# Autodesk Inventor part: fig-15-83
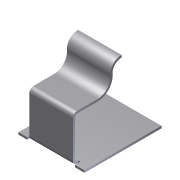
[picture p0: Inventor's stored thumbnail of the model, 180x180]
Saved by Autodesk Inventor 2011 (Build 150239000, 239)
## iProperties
Shininess: 77.0
Angle Display Precision: 2
Document Length Units: 11269
Document Angle Units: 11279
Document Time Units: 11290
Document Mass Units: 11283
Document Length Units Precision: 3
Document Angle Units Precision: 2
Compacted: True
Created: 2002-04
Part Number: fig-15-83
Document SubType Name: Sheet Metal
Density: 1 g/cm^3
Sheet Metal Rule: Default
Density: 0.0
Volumn: 0.0
Area: 0.0
PropertySet Name: Model Information
Control State: 0
Master: False
Checked Out: False
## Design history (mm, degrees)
node "Face1"
  sketch "Sketch1"
    geometry: L1 (-24.824, 17.882)-(5.529, 17.882); L2 (5.529, 17.882)-(5.529, -17.529); L3 (5.529, -17.529)-(-24.824, -17.529); L4 (-24.824, -17.529)-(-24.824, 17.882)
    constraints: 8 end point, 2 parallel, 1 horizontal, 1 perpendicular
node "Flange1"
node "Contour Flange6"
  sketch "Sketch5"
    geometry: L1 (0, 1)-(0, 11.431); A1 r 5.855 centre (-5.855, 11.431) between (0, 11.431) and (-6.422, 17.259); A2 r 5.142 centre (-6.92, 22.376) between (-12.062, 22.382) and (-6.422, 17.259)
    constraints: 4 point on circle, 2 centre point, 2 end point, 2 tangent
body "Solid1"
face "Plate1" dims "Thickness" = 1
sketch "Sketch3"
  geometry: L1 (25.353, 0)-(5.353, 0); L2 (5.353, 0)-(5.353, 20); L3 (5.353, 20)-(25.353, 20); L4 (25.353, 20)-(25.353, 0)
  constraints: 8 end point
face "Plate3" dims "d5" = 20, "d6" = 90 deg, "d7" = 1 (= BendRadius), "d11" = 5, "d12" = 20, "Thickness" = 1, "MinimumRemnant" = 2 (= 2 x Thickness), "BendReliefWidth" = 1 (= Thickness)
bend "Bend2" dims "d5" = 20, "d6" = 90 deg, "d7" = 1 (= BendRadius), "d21" = 1 (= BendReliefWidth), "d22" = 0.5 (= BendReliefDepth), "d23" = 2 (= MinimumRemnant), "SeamGap" = 0.01, "Thickness" = 1, "MinimumRemnant" = 2 (= 2 x Thickness), "BendReliefWidth" = 1 (= Thickness), "TransitionRadius" = 1 (= BendRadius)
face "Plate8" dims "d33" = 1 (= BendReliefWidth), "d34" = 0.5 (= BendReliefDepth), "d35" = 2 (= MinimumRemnant), "d36" = 1 (= BendRadius), "d37" = 1 (= BendRadius), "d38" = 1, "d39" = 4 (= CornerReliefSize), "d40" = 1 (= GapSize), "d41" = 1 (= JacobiRadiusSize), "SeamGap" = 0.01, "Thickness" = 1
bend "Bend7" dims "d33" = 1 (= BendReliefWidth), "d34" = 0.5 (= BendReliefDepth), "d35" = 2 (= MinimumRemnant), "d36" = 1 (= BendRadius), "d37" = 1 (= BendRadius), "d38" = 1, "SeamGap" = 0.01, "Thickness" = 1
feature "Corner1" dims "d38" = 1, "d39" = 4 (= CornerReliefSize), "d40" = 1 (= GapSize), "d41" = 1 (= JacobiRadiusSize)
other parameters: "BendRadius" = 1 (= Thickness), "BendReliefDepth" = 0.5 (= 0.5 x Thickness), "CornerReliefSize" = 4 (= 4 x Thickness), "d0" = 1 (= BendRadius), "d4" = 1 (= BendRadius), "JacobiRadiusSize" = 1 (= Thickness), "GapSize" = 1 (= Thickness)
